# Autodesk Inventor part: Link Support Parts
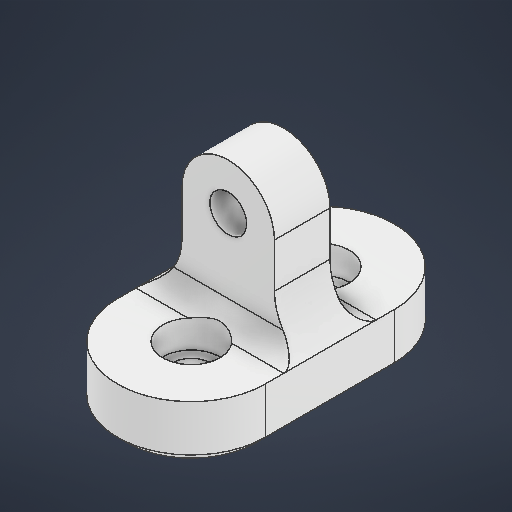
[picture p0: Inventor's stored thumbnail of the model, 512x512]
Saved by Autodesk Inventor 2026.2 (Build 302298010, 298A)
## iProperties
Created: 2026-05
Part Number: Link Support Parts
Material: ABS 플라스틱
Document SubType Name: Modeling
Designer: work
Density: 1.06 g/cm^3
Appearance: 매끄러움 - 흰색
Author: work
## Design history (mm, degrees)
sketch "스케치1"
  geometry: L1 (0, 7)-(0, -7); L2 (0, 7)-(0, -7); L3 (-8, 7)-(-8, -7); L4 (8, -7)-(8, 7); C1 r 2 at (0, 7); C2 r 2 at (0, -7); A1 r 8 centre (0, 7) between (8, 7) and (-8, 7); A2 r 8 centre (0, -7) between (-8, -7) and (8, -7); 2 further points
  constraints: 10 end point, 4 centre point, 4 point on circle, 4 tangent, 2 coincident, 2 equal length, 2 midpoint, 1 vertical
  dimensions: "d0" = 14 distance of L1.start L1.end; "d1" = 4 diameter of C1; "d2" = 4 diameter of C2; "d3" = 8 radius of A2
extrude "돌출1" new body sketch "스케치1" distance "d4" = 6; taper "d5" = 0 deg
sketch "스케치2"
  geometry: C1 r 2 at (0, -7) reference; C2 r 2 at (0, 7) reference; 3 further points
  constraints: 2 coincident
hole "구멍1" sketch "스케치2" at (0, -7), (0, 7) diameter "d6" = 4; stored, may be unused: countersink angle "d10" = 90 deg, drill point angle "d12" = 0 deg; dims "d7" = 5, "d8" = 6.2, "d9" = 3, "d11" = 5
sketch "스케치3"
  geometry: L1 (8, 6)-(-8, 6) reference; L2 (0, 6)-(0, 16); L3 (5, 6)-(5, 16); L4 (-5, 16)-(-5, 6); C1 r 2 at (0, 16); A1 r 5 centre (0, 6) between (-5, 6) and (5, 6); A2 r 5 centre (0, 16) between (5, 16) and (-5, 16); 2 further points
  constraints: 8 end point, 4 point on circle, 4 tangent, 3 centre point, 2 midpoint, 1 coincident, 1 parallel, 1 perpendicular
  dimensions: "d13" = 4 diameter of C1; "d14" = 10 distance of L2.start L2.end; "d15" = 5 radius of A2
extrude "돌출2" join sketch "스케치3" stored distance "d16" = 6; taper "d17" = 0 deg
fillet "모깎기1" dims "d18" = 6
fillet "모깎기2" dims "d19" = 2
chamfer "모따기1" distance "d20" = 1; stored, may be unused: second distance "d21" = 2, angle "d22" = 45 deg
node "솔리드1"
feature "A9D066F2-1C7D-4E18-AEED-F7BC21143FA4" dims "d6" = 4, "d7" = 5, "d8" = 6.2, "d9" = 3, "d10" = 90 deg, "d11" = 5, "d12" = 0
